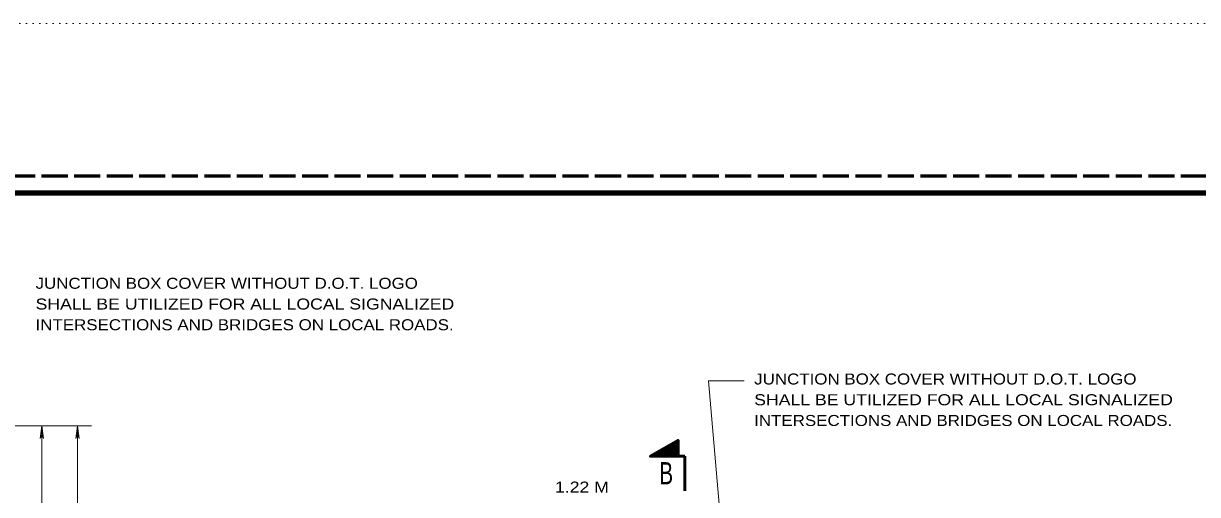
# Model space of a CAD drawing. Extents: x 312583 to 312854, y 144419 to 144597.
# Drawn here: x 312691.2 to 312772.3, y 144564.2 to 144596.8 of the extents above; entities that cross this region are included whole.
import ezdxf
from ezdxf.enums import TextEntityAlignment as Align

# ---------------------------------------------------------------- set-up
doc = ezdxf.new("R2010")
doc.units = 0
doc.header["$LTSCALE"] = 0.3
doc.linetypes.add('DOTTED', pattern=[1.5, 0.3, -1.2])
doc.linetypes.add('LONG_DASHED', pattern=[7.5, 6, -1.5])
for name, color, linetype, lineweight in [('1', 7, 'Continuous', 25), ('2', 7, 'Continuous', 13), ('63', 7, 'DOTTED', 13)]:
    doc.layers.add(name, color=color, linetype=linetype, lineweight=lineweight)

msp = doc.modelspace()

# ---------------------------------------------------------------- linework, layer by layer
at = {"layer": '1', "linetype": 'LONG_DASHED', "lineweight": 60}
msp.add_line((312851.75, 144586.2246), (312583.526, 144586.2246), dxfattribs=at)
at = {"layer": '1', "lineweight": 35}
for p, q in [((312736.439, 144567.2653), (312736.1324, 144567.7943)), ((312736.439, 144567.3113), (312736.1554, 144567.8019)), ((312736.439, 144567.3649), (312736.1707, 144567.8173)), ((312736.439, 144567.4109), (312736.1937, 144567.8249)), ((312736.439, 144567.4569), (312736.2167, 144567.8403)), ((312736.439, 144567.5106), (312736.232, 144567.8479)), ((312736.439, 144567.5566), (312736.2627, 144567.8633)), ((312736.439, 144567.6026), (312736.278, 144567.8709)), ((312736.439, 144567.6486), (312736.301, 144567.8863)), ((312736.439, 144567.7023), (312736.324, 144567.8939)), ((312736.439, 144567.7406), (312736.3394, 144567.9093)), ((312736.439, 144567.7943), (312736.3624, 144567.9169)), ((312736.439, 144567.8403), (312736.3854, 144567.9323)), ((312736.439, 144567.8939), (312736.4007, 144567.9476)), ((312736.439, 144567.9399), (312736.4237, 144567.9553)), ((312734.8137, 144566.8589), (312734.7447, 144566.9893)), ((312734.8444, 144566.8589), (312734.7677, 144566.9969)), ((312734.8674, 144566.8589), (312734.783, 144567.0123)), ((312734.898, 144566.8589), (312734.806, 144567.0276)), ((312734.9287, 144566.8589), (312734.829, 144567.0353)), ((312734.9594, 144566.8589), (312734.8444, 144567.0506)), ((312734.9824, 144566.8589), (312734.8674, 144567.0659)), ((312735.013, 144566.8589), (312734.8904, 144567.0736)), ((312735.036, 144566.8589), (312734.9057, 144567.0889)), ((312735.0667, 144566.8589), (312734.9287, 144567.0966)), ((312735.0974, 144566.8589), (312734.9517, 144567.1119)), ((312735.1204, 144566.8589), (312734.967, 144567.1196)), ((312735.151, 144566.8589), (312734.9977, 144567.1349)), ((312735.174, 144566.8589), (312735.013, 144567.1426)), ((312735.2047, 144566.8589), (312735.036, 144567.1579)), ((312735.2354, 144566.8589), (312735.059, 144567.1656)), ((312735.2584, 144566.8589), (312735.0744, 144567.1809)), ((312735.289, 144566.8589), (312735.0974, 144567.1886)), ((312735.312, 144566.8589), (312735.1204, 144567.2039)), ((312735.3427, 144566.8589), (312735.1357, 144567.2193)), ((312735.3657, 144566.8589), (312735.1587, 144567.2269)), ((312735.3964, 144566.8589), (312735.1817, 144567.2423)), ((312735.427, 144566.8589), (312735.197, 144567.2576)), ((312735.4577, 144566.8589), (312735.22, 144567.2653)), ((312735.4807, 144566.8589), (312735.243, 144567.2806)), ((312735.5037, 144566.8589), (312735.266, 144567.2883)), ((312735.5344, 144566.8589), (312735.2814, 144567.3036)), ((312735.565, 144566.8589), (312735.3044, 144567.3113)), ((312735.588, 144566.8589), (312735.3274, 144567.3266)), ((312735.6187, 144566.8589), (312735.3427, 144567.3343)), ((312735.6494, 144566.8589), (312735.3657, 144567.3496)), ((312735.6724, 144566.8589), (312735.3887, 144567.3573)), ((312735.703, 144566.8589), (312735.404, 144567.3726)), ((312735.7337, 144566.8589), (312735.427, 144567.3803)), ((312735.7567, 144566.8589), (312735.45, 144567.3956)), ((312735.7874, 144566.8666), (312735.4654, 144567.4109)), ((312735.8104, 144566.8589), (312735.496, 144567.4186)), ((312735.841, 144566.8589), (312735.5114, 144567.4339)), ((312735.864, 144566.8589), (312735.5344, 144567.4416)), ((312735.8947, 144566.8589), (312735.5574, 144567.4569)), ((312735.9254, 144566.8589), (312735.5727, 144567.4646)), ((312735.956, 144566.8589), (312735.5957, 144567.4799)), ((312735.979, 144566.8589), (312735.6187, 144567.4876)), ((312736.002, 144566.8589), (312735.634, 144567.5029)), ((312736.0327, 144566.8666), (312735.657, 144567.5106)), ((312736.0634, 144566.8589), (312735.68, 144567.5259)), ((312736.0864, 144566.8589), (312735.6954, 144567.5336)), ((312736.117, 144566.8589), (312735.7184, 144567.5489)), ((312736.1477, 144566.8589), (312735.7414, 144567.5643)), ((312736.1707, 144566.8589), (312735.7644, 144567.5719)), ((312736.2014, 144566.8589), (312735.7797, 144567.5873)), ((312736.232, 144566.8589), (312735.8027, 144567.6026)), ((312736.255, 144566.8666), (312735.8257, 144567.6103)), ((312736.2857, 144566.8666), (312735.841, 144567.6256)), ((312736.3087, 144566.8589), (312735.864, 144567.6333)), ((312736.3394, 144566.8589), (312735.887, 144567.6486)), ((312736.3624, 144566.8589), (312735.9024, 144567.6563)), ((312736.393, 144566.8589), (312735.9254, 144567.6716)), ((312736.4237, 144566.8589), (312735.9484, 144567.6793)), ((312736.439, 144566.8819), (312735.9637, 144567.6946)), ((312736.439, 144566.9356), (312735.9944, 144567.7023)), ((312736.439, 144566.9739), (312736.0097, 144567.7176)), ((312736.439, 144567.0276), (312736.0327, 144567.7253)), ((312736.439, 144567.0736), (312736.0557, 144567.7406)), ((312736.439, 144567.1196), (312736.071, 144567.7559)), ((312736.439, 144567.1656), (312736.094, 144567.7636)), ((312736.439, 144567.2193), (312736.117, 144567.7789)), ((312734.5377, 144566.8589), (312734.5377, 144566.8743)), ((312734.5684, 144566.8589), (312734.5607, 144566.8819)), ((312734.599, 144566.8589), (312734.576, 144566.8973)), ((312734.622, 144566.8589), (312734.599, 144566.9049)), ((312734.6527, 144566.8589), (312734.622, 144566.9203)), ((312734.6757, 144566.8589), (312734.6374, 144566.9279)), ((312734.7064, 144566.8589), (312734.6604, 144566.9433)), ((312734.737, 144566.8589), (312734.6834, 144566.9509)), ((312734.7677, 144566.8589), (312734.6987, 144566.9663)), ((312734.7907, 144566.8589), (312734.7217, 144566.9739))]:
    msp.add_line(p, q, dxfattribs=at)
at = {"layer": '1', "lineweight": 53}
for p in [(312736.439, 144566.8589), (312736.9144, 144564.4669)]:
    msp.add_line(p, (312736.9144, 144566.8589), dxfattribs=at)
at = {"layer": '1', "lineweight": 158}
msp.add_lwpolyline([(312616.5, 144423.1446), (312616.5, 144585.0846), (312849, 144585.0846)], dxfattribs=at)
at = {"layer": '1', "lineweight": 53}
msp.add_lwpolyline([(312736.439, 144566.8589), (312736.439, 144567.9706), (312734.5224, 144566.8589)], close=True, dxfattribs=at)
at = {"layer": '2'}
for p, q in [((312685.7337, 144568.9533), (312695.9079, 144568.9533)), ((312692.4653, 144568.9533), (312692.358, 144568.087)), ((312692.4653, 144568.9533), (312692.5727, 144568.087)), ((312694.9273, 144568.9533), (312694.8199, 144568.087)), ((312694.9273, 144540.2033), (312694.9273, 144568.9533)), ((312694.9273, 144568.9533), (312695.0346, 144568.087)), ((312692.358, 144568.087), (312692.4653, 144568.363)), ((312692.5727, 144568.087), (312692.4653, 144568.363)), ((312694.8199, 144568.087), (312694.9273, 144568.363)), ((312695.0346, 144568.087), (312694.9273, 144568.363))]:
    msp.add_line(p, q, dxfattribs=at)
for points in [[(312741.0021, 144572.0671), (312738.5537, 144572.0671), (312740.4334, 144550.1916)], [(312692.4653, 144535.174), (312692.4653, 144554.5783), (312692.4653, 144568.9533)]]:
    msp.add_lwpolyline(points, dxfattribs=at)
at = {"layer": '63'}
msp.add_line((312601.2, 144596.7846), (312853.5, 144596.7846), dxfattribs=at)

# ---------------------------------------------------------------- texts
at = {"layer": '1', "width": 0.7}
msp.add_text('B', height=1.533, dxfattribs=at).set_placement((312735.6225, 144564.9193), align=Align.CENTER)
at = {"layer": '2'}
for s, width, p in [('JUNCTION BOX COVER WITHOUT D.O.T. LOGO', 1.15, (312692.0312, 144578.4395)), ('SHALL BE UTILIZED FOR ALL LOCAL SIGNALIZED', 1.2, (312692.0312, 144577.0059)), ('INTERSECTIONS AND BRIDGES ON LOCAL ROADS.', 1.15, (312692.0312, 144575.5722)), ('JUNCTION BOX COVER WITHOUT D.O.T. LOGO', 1.15, (312741.7044, 144571.8203)), ('SHALL BE UTILIZED FOR ALL LOCAL SIGNALIZED', 1.2, (312741.7044, 144570.3866)), ('INTERSECTIONS AND BRIDGES ON LOCAL ROADS.', 1.15, (312741.7044, 144568.953)), ('1.22 M', 1.2, (312727.9332, 144564.3492))]:
    msp.add_text(s, height=0.76, dxfattribs=dict(at, width=width)).set_placement(p)

doc.saveas('drawing.dxf')
